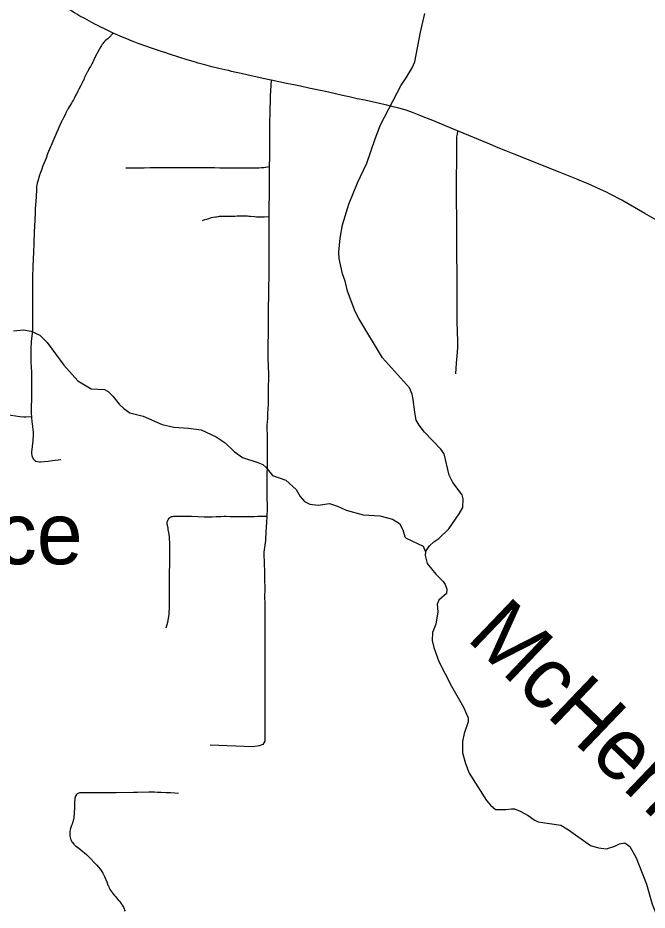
# Model space of a CAD drawing. Extents: x -19 to 366, y -4 to 359.
# Drawn here: x 143.966 to 144.78, y 188.535 to 189.689 of the extents above; entities that cross this region are included whole.
import ezdxf

# ---------------------------------------------------------------- set-up
doc = ezdxf.new("R2010")
doc.units = 0
for name, color, linetype in [('R_ROW', 7, 'Continuous'), ('R_ROW Annot', 7, 'Continuous'), ('R_Temp Easement', 7, 'Continuous'), ('Sheet Fence', 7, 'Continuous')]:
    doc.layers.add(name, color=color, linetype=linetype)

msp = doc.modelspace()

# ---------------------------------------------------------------- linework, layer by layer
at = {"layer": 'R_ROW'}
for points in [[(144.0894, 189.669), (144.0789, 189.674), (144.0724, 189.6772), (144.0695, 189.6786), (144.0673, 189.6797), (144.0616, 189.6827), (144.0524, 189.6876), (144.0463, 189.6909), (144.0424, 189.6932), (144.0391, 189.6952), (144.0312, 189.7001), (144.0265, 189.7032), (144.0193, 189.7083), (144.0142, 189.7118), (144.0095, 189.7152), (144.0064, 189.7175), (144.0011, 189.7214), (143.9869, 189.7317), (143.9768, 189.7391)], [(144.0894, 189.669), (144.0838, 189.6629), (144.0834, 189.6626), (144.0822, 189.6616), (144.0809, 189.6606), (144.079, 189.6589), (144.0781, 189.658), (144.0774, 189.6572), (144.0769, 189.6567), (144.0758, 189.6553), (144.0753, 189.6547), (144.0747, 189.6538), (144.074, 189.6528), (144.0721, 189.6496), (144.0709, 189.6475), (144.0689, 189.6438), (144.0679, 189.6419), (144.0648, 189.6357), (144.0641, 189.6342), (144.0628, 189.6315), (144.0616, 189.6291), (144.0598, 189.6259), (144.0589, 189.6245), (144.0579, 189.6225), (144.0563, 189.6194), (144.0557, 189.6184), (144.0539, 189.6148), (144.0531, 189.6131), (144.0519, 189.6105), (144.0512, 189.6091), (144.0502, 189.6069), (144.0496, 189.606), (144.049, 189.6048), (144.0473, 189.6013), (144.0449, 189.5963), (144.0436, 189.5937), (144.043, 189.5924), (144.0414, 189.5894), (144.0407, 189.5881), (144.0391, 189.5852), (144.0378, 189.5828), (144.0367, 189.5808), (144.0354, 189.5785), (144.0333, 189.5749), (144.0324, 189.5735), (144.031, 189.5713), (144.0304, 189.5703), (144.0298, 189.5693), (144.0286, 189.5666), (144.0281, 189.5656), (144.0274, 189.5641), (144.0256, 189.5602), (144.0237, 189.5569), (144.0231, 189.556), (144.023, 189.5556)], [(144.2933, 189.6081), (144.287, 189.6095), (144.2621, 189.615), (144.2549, 189.6165), (144.2482, 189.618), (144.2423, 189.6194), (144.2381, 189.6204), (144.2335, 189.6215), (144.2259, 189.6232), (144.2169, 189.6254), (144.2079, 189.6277), (144.1992, 189.6302), (144.1957, 189.6312), (144.1911, 189.6326), (144.1834, 189.6349), (144.1756, 189.6375), (144.162, 189.6418), (144.1558, 189.6438), (144.1512, 189.6453), (144.1491, 189.646), (144.1399, 189.6491), (144.1301, 189.6526), (144.1216, 189.6556), (144.1173, 189.6572), (144.1116, 189.6594), (144.1092, 189.6604), (144.1054, 189.662), (144.0983, 189.665), (144.0954, 189.6662), (144.0894, 189.669)], [(144.2933, 189.6081), (144.2923, 189.5876), (144.2917, 189.5649), (144.2915, 189.5545), (144.2915, 189.543), (144.2912, 189.5311), (144.2912, 189.5236), (144.2912, 189.5167), (144.2912, 189.5093), (144.2911, 189.4961)], [(144.5346, 189.5424), (144.5005, 189.5566), (144.4943, 189.5591), (144.4847, 189.5629), (144.4763, 189.5661), (144.468, 189.5691), (144.4585, 189.5719), (144.4496, 189.5742), (144.4432, 189.5757), (144.4147, 189.582), (144.4048, 189.5841), (144.3945, 189.5864), (144.3855, 189.5884), (144.375, 189.5908), (144.3636, 189.5932), (144.342, 189.5977), (144.3314, 189.6001), (144.3227, 189.6018), (144.3135, 189.6038), (144.2933, 189.6081)], [(144.023, 189.5556), (144.019, 189.5467), (144.0181, 189.5448), (144.0163, 189.5406), (144.0097, 189.5256), (144.0089, 189.5237), (144.0081, 189.5217), (144.0045, 189.5128), (144.0024, 189.5074), (143.9998, 189.501), (143.9984, 189.4972), (143.9965, 189.4916), (143.9954, 189.4888), (143.9941, 189.4851), (143.9916, 189.4775), (143.9913, 189.4763), (143.991, 189.4748), (143.9905, 189.4727), (143.9901, 189.4701), (143.9899, 189.4674), (143.9895, 189.4568), (143.9892, 189.452), (143.9885, 189.4414), (143.9883, 189.4371), (143.9877, 189.427), (143.987, 189.4121), (143.9868, 189.3974), (143.9862, 189.3854), (143.9858, 189.3769), (143.9854, 189.3664), (143.9851, 189.3542), (143.985, 189.3447), (143.9849, 189.3373), (143.9849, 189.3272), (143.9848, 189.3108), (143.9849, 189.3049), (143.9849, 189.3012), (143.985, 189.2936), (143.9849, 189.2922), (143.9847, 189.2838), (143.9845, 189.2811), (143.9836, 189.2735), (143.9833, 189.2701), (143.9826, 189.2599), (143.9826, 189.2557), (143.9827, 189.2446), (143.9833, 189.2361), (143.9835, 189.2319), (143.9837, 189.2136), (143.9837, 189.2059), (143.9837, 189.2005), (143.9832, 189.1809), (143.9833, 189.1767), (143.9834, 189.1733)], [(144.7917, 189.4269), (144.7767, 189.4356), (144.747, 189.4527), (144.732, 189.4607), (144.727, 189.4632), (144.7195, 189.4668), (144.7138, 189.4694), (144.7079, 189.472), (144.7013, 189.4748), (144.6949, 189.4774), (144.6885, 189.4799), (144.667, 189.4885), (144.6077, 189.5122), (144.597, 189.5165), (144.5869, 189.5206), (144.5761, 189.5251), (144.5346, 189.5424)], [(144.2911, 189.4961), (144.2839, 189.4949), (144.2809, 189.4946), (144.2776, 189.4944), (144.2739, 189.4943), (144.2702, 189.4942), (144.2628, 189.4942), (144.2557, 189.4942), (144.2483, 189.4943), (144.243, 189.4943), (144.2345, 189.4943), (144.2271, 189.4944), (144.2202, 189.4946), (144.2107, 189.4946), (144.2017, 189.4945), (144.1931, 189.4946), (144.1863, 189.4947), (144.1778, 189.4947), (144.1704, 189.4946), (144.163, 189.4946), (144.1561, 189.4945), (144.1492, 189.4945), (144.1418, 189.4945), (144.137, 189.4945), (144.1291, 189.4944), (144.1222, 189.4944), (144.1158, 189.4944), (144.1089, 189.4943), (144.1055, 189.4941)], [(144.2911, 189.4961), (144.291, 189.4874), (144.291, 189.4809), (144.291, 189.4736), (144.2909, 189.4638), (144.2908, 189.4554), (144.2906, 189.4489), (144.2906, 189.4319)], [(144.2906, 189.4319), (144.2905, 189.4169), (144.2903, 189.4052), (144.2905, 189.3895), (144.2904, 189.3653), (144.2903, 189.357), (144.2903, 189.3505), (144.2902, 189.3444), (144.2901, 189.3379), (144.29, 189.3314), (144.2898, 189.3118), (144.2898, 189.2974), (144.2898, 189.2858), (144.2897, 189.2802), (144.2893, 189.2668), (144.2892, 189.2584), (144.2891, 189.2496), (144.2896, 189.2371), (144.29, 189.2287), (144.29, 189.2222), (144.2898, 189.2121), (144.2895, 189.2023), (144.2894, 189.1971), (144.2894, 189.1892), (144.2889, 189.1771), (144.2886, 189.1706), (144.288, 189.1618), (144.288, 189.159), (144.2882, 189.1479), (144.2882, 189.1391), (144.2881, 189.1312), (144.2881, 189.1112), (144.2878, 189.0954), (144.2878, 189.0885), (144.2878, 189.0817), (144.2878, 189.0738), (144.288, 189.0674), (144.2881, 189.059), (144.2881, 189.0538), (144.2878, 189.0443)], [(144.2878, 189.0443), (144.2875, 189.0359), (144.2872, 189.0309), (144.2863, 189.0149), (144.2861, 189.0128), (144.2839, 188.9979), (144.2839, 188.997), (144.2845, 188.9821), (144.2849, 188.9736), (144.2849, 188.9646), (144.2851, 188.9492), (144.285, 188.9412), (144.2852, 188.9303), (144.2855, 188.9253)]]:
    msp.add_lwpolyline(points, dxfattribs=at)
at = {"layer": 'R_ROW Annot'}
for points in [[(144.5346, 189.5424), (144.534, 189.5384), (144.5333, 189.5347), (144.5331, 189.533), (144.5331, 189.5295), (144.5329, 189.5063), (144.5327, 189.4796), (144.5327, 189.471), (144.5329, 189.411), (144.5329, 189.3918), (144.5329, 189.3865), (144.533, 189.383), (144.5332, 189.3728), (144.5334, 189.3679), (144.5335, 189.3619), (144.5335, 189.3579), (144.5334, 189.3461), (144.5334, 189.3351), (144.5334, 189.3249), (144.5334, 189.3095), (144.5335, 189.3028), (144.5336, 189.2979), (144.5337, 189.294), (144.5338, 189.2843), (144.534, 189.2792), (144.5342, 189.2743), (144.5344, 189.271), (144.5346, 189.2664), (144.5345, 189.263), (144.534, 189.2565), (144.5327, 189.2423), (144.5319, 189.2284)], [(144.2047, 189.4267), (144.2076, 189.4277), (144.2101, 189.4284), (144.2131, 189.4294), (144.2163, 189.4303), (144.2186, 189.4308), (144.2216, 189.4313), (144.2229, 189.4315), (144.2253, 189.4318), (144.2268, 189.432), (144.2287, 189.4321), (144.2315, 189.4322), (144.2336, 189.4322), (144.2362, 189.4322), (144.24, 189.4321), (144.2416, 189.4321), (144.2445, 189.4321), (144.2466, 189.4322), (144.2495, 189.4325), (144.2519, 189.4326), (144.2533, 189.4326), (144.2554, 189.4326), (144.2572, 189.4327), (144.2587, 189.4327), (144.2627, 189.4325), (144.2648, 189.4324), (144.2669, 189.4322), (144.272, 189.4317), (144.2745, 189.4315), (144.2767, 189.4314), (144.2795, 189.4313), (144.2824, 189.4312), (144.2843, 189.4313), (144.2906, 189.4319)], [(143.9037, 189.1612), (143.9061, 189.1626), (143.9089, 189.1642), (143.9109, 189.1655), (143.9119, 189.1664), (143.914, 189.1679), (143.9166, 189.1698), (143.9176, 189.1705), (143.9188, 189.1717), (143.9201, 189.1729), (143.9236, 189.1755), (143.9241, 189.1757), (143.9254, 189.1764), (143.9258, 189.1766), (143.9266, 189.1768), (143.9281, 189.1768), (143.9319, 189.1765), (143.9403, 189.1759), (143.9538, 189.1755), (143.9573, 189.1751), (143.9683, 189.1734), (143.9735, 189.1726), (143.9761, 189.1726), (143.9834, 189.1733)], [(143.9834, 189.1733), (143.9834, 189.173), (143.9841, 189.1661), (143.9844, 189.164), (143.9849, 189.1598), (143.9856, 189.1528), (143.9857, 189.1498), (143.9852, 189.1419), (143.9838, 189.1269), (143.9838, 189.1253), (143.984, 189.1227), (143.9843, 189.1216), (143.9858, 189.1187), (143.9861, 189.1182), (143.9866, 189.1177), (143.988, 189.1164), (143.9894, 189.1155), (143.9898, 189.1153), (143.9918, 189.115), (143.9939, 189.1148), (143.9954, 189.1148), (144.005, 189.1156), (144.0107, 189.1163), (144.0214, 189.1177)], [(144.1576, 188.9002), (144.1598, 188.9075), (144.1603, 188.9095), (144.1612, 188.9152), (144.1615, 188.9172), (144.1621, 188.928), (144.1619, 188.9379), (144.1619, 188.9461), (144.162, 188.9706), (144.1621, 188.9742), (144.1624, 188.9798), (144.1624, 188.9821), (144.1625, 188.988), (144.1626, 188.9967), (144.1626, 188.9985), (144.1625, 189.0074), (144.1624, 189.0102), (144.1621, 189.015), (144.1619, 189.0173), (144.1614, 189.0211), (144.1605, 189.0272), (144.1601, 189.0295), (144.159, 189.034), (144.1591, 189.0354), (144.1592, 189.0369), (144.1597, 189.0389), (144.1602, 189.0401), (144.1606, 189.0407), (144.1614, 189.0416), (144.1625, 189.0426), (144.1642, 189.0437), (144.1646, 189.0438), (144.1655, 189.044), (144.1672, 189.0442), (144.1718, 189.0443), (144.1779, 189.0443), (144.1818, 189.0443), (144.1854, 189.0444), (144.1884, 189.0443), (144.1904, 189.0442), (144.207, 189.0433), (144.2106, 189.0433), (144.2172, 189.0436), (144.2223, 189.0439), (144.2282, 189.0441), (144.2323, 189.0442), (144.2352, 189.0443), (144.2404, 189.0441), (144.249, 189.0438), (144.2526, 189.0438), (144.2677, 189.0441), (144.2719, 189.0441), (144.2758, 189.0442), (144.2878, 189.0443)], [(144.2855, 188.9253), (144.2851, 188.7534), (144.2827, 188.7493), (144.278, 188.7475), (144.2698, 188.7463), (144.2144, 188.7481)], [(144.1737, 188.686), (144.1689, 188.6862), (144.1635, 188.6865), (144.1579, 188.6868), (144.1514, 188.687), (144.1466, 188.6873), (144.1427, 188.6874), (144.1376, 188.6876), (144.1351, 188.6876), (144.1207, 188.6872), (144.1154, 188.6871), (144.0931, 188.6867), (144.0883, 188.6867), (144.0847, 188.6867), (144.0802, 188.6867), (144.072, 188.6865), (144.0658, 188.6865), (144.0537, 188.6866), (144.0517, 188.6867), (144.0478, 188.6868), (144.0458, 188.6865), (144.0447, 188.6863), (144.0436, 188.6858), (144.0427, 188.6852), (144.0418, 188.6845), (144.0405, 188.6822), (144.04, 188.6811), (144.0397, 188.68), (144.0396, 188.6787), (144.0394, 188.6748), (144.0393, 188.6734), (144.0391, 188.6703), (144.039, 188.6663), (144.0389, 188.6617), (144.0388, 188.6591), (144.0385, 188.6563), (144.0383, 188.6545), (144.0378, 188.652), (144.0376, 188.6512), (144.0373, 188.6502), (144.0368, 188.6482), (144.0361, 188.6461), (144.0355, 188.6443), (144.0345, 188.6418), (144.034, 188.6404), (144.0336, 188.639), (144.0333, 188.637), (144.0331, 188.6351), (144.033, 188.6328), (144.033, 188.6314), (144.0337, 188.6288), (144.0342, 188.6272), (144.0348, 188.6256), (144.0358, 188.6235), (144.0365, 188.6224), (144.0384, 188.6202), (144.0396, 188.6191), (144.041, 188.6179), (144.0431, 188.6163), (144.0447, 188.6151), (144.0473, 188.6132), (144.0549, 188.6069), (144.0577, 188.6041), (144.0674, 188.5942), (144.0682, 188.5932), (144.07, 188.591), (144.0726, 188.5876), (144.0737, 188.5861), (144.0757, 188.583), (144.0768, 188.581), (144.0781, 188.5785), (144.0794, 188.5754), (144.0798, 188.5745), (144.0808, 188.5717), (144.0813, 188.5705), (144.0825, 188.5674), (144.083, 188.5664), (144.0836, 188.5649), (144.0841, 188.5638), (144.0854, 188.5613), (144.0864, 188.5596), (144.0877, 188.5579), (144.0885, 188.5568), (144.091, 188.5538), (144.0921, 188.5525), (144.0963, 188.5477), (144.097, 188.547), (144.0977, 188.5461), (144.0993, 188.5441), (144.1005, 188.5423), (144.101, 188.5416), (144.1017, 188.5403), (144.1024, 188.539), (144.1034, 188.5368), (144.104, 188.5351), (144.1045, 188.5335)]]:
    msp.add_lwpolyline(points, dxfattribs=at)
at = {"layer": 'R_Temp Easement'}
for points in [[(144.4932, 188.9982), (144.4983, 189.006), (144.5037, 189.0112), (144.5104, 189.0157), (144.5232, 189.0279), (144.5364, 189.0472), (144.5411, 189.0557), (144.5418, 189.0666), (144.5405, 189.0721), (144.5285, 189.0878), (144.5235, 189.0974), (144.5171, 189.1249), (144.5127, 189.131), (144.4919, 189.1531), (144.4849, 189.1618), (144.4811, 189.1683), (144.4791, 189.1787), (144.4771, 189.195), (144.476, 189.2022), (144.4723, 189.2102), (144.4376, 189.2491), (144.4069, 189.2997), (144.4019, 189.309), (144.3923, 189.3351), (144.3892, 189.3482), (144.3856, 189.3575), (144.3813, 189.3774), (144.3809, 189.3856), (144.3825, 189.4036), (144.3857, 189.4211), (144.3941, 189.4479), (144.4052, 189.4751), (144.4172, 189.5008), (144.4279, 189.5324), (144.435, 189.5504), (144.4614, 189.6016), (144.4682, 189.6109), (144.4757, 189.6241), (144.4791, 189.6319), (144.4867, 189.6703), (144.4923, 189.6944)], [(143.9603, 189.2838), (143.9732, 189.2853), (143.9833, 189.2837), (143.9945, 189.2782), (144.0038, 189.2688), (144.0256, 189.2396), (144.0433, 189.2194), (144.0606, 189.2092), (144.0779, 189.2083), (144.0827, 189.2057), (144.0888, 189.1996), (144.097, 189.1892), (144.1029, 189.1836), (144.1109, 189.1779), (144.1278, 189.1738), (144.1527, 189.1627), (144.1675, 189.1593), (144.1868, 189.1581), (144.203, 189.1559), (144.2224, 189.147), (144.2342, 189.1393), (144.2458, 189.1278), (144.2566, 189.12), (144.2764, 189.1137)], [(144.2764, 189.1137), (144.2825, 189.111), (144.2867, 189.1076), (144.2952, 189.097), (144.3125, 189.0908), (144.3259, 189.0788), (144.3308, 189.0697), (144.3367, 189.0632), (144.3434, 189.0597), (144.3544, 189.0586), (144.3688, 189.0609), (144.3793, 189.0575), (144.3905, 189.0523), (144.4125, 189.0463), (144.4342, 189.0447), (144.4503, 189.0407), (144.4594, 189.0347), (144.4638, 189.0267), (144.4665, 189.0178), (144.468, 189.0161), (144.4899, 189.0056), (144.4932, 188.9982), (144.4924, 188.9936), (144.4953, 188.9832), (144.5062, 188.9694), (144.5159, 188.9601), (144.5186, 188.9562), (144.5205, 188.9501), (144.52, 188.9446), (144.5101, 188.9356), (144.5083, 188.9305), (144.5089, 188.9208), (144.5063, 188.9047), (144.5022, 188.8938), (144.5016, 188.8838), (144.5036, 188.8745), (144.5101, 188.8563), (144.5265, 188.8246), (144.542, 188.7975), (144.5482, 188.7835), (144.548, 188.7786), (144.5431, 188.7636), (144.5409, 188.7529), (144.541, 188.7383), (144.5446, 188.7246), (144.5496, 188.7123), (144.572, 188.6767), (144.5769, 188.6709), (144.5834, 188.6652), (144.5969, 188.6651), (144.6041, 188.6662), (144.6081, 188.6659), (144.6153, 188.6632), (144.6259, 188.6572), (144.6335, 188.6517), (144.6387, 188.6493), (144.6679, 188.6447), (144.6778, 188.639), (144.7063, 188.6186), (144.7168, 188.6155), (144.7269, 188.6145), (144.738, 188.6178), (144.7439, 188.6209), (144.7507, 188.622), (144.7572, 188.6175), (144.7654, 188.6026), (144.7787, 188.5684)], [(144.7787, 188.5684), (144.786, 188.5426), (144.7958, 188.5196), (144.8023, 188.4959), (144.8057, 188.4886), (144.813, 188.4818)]]:
    msp.add_lwpolyline(points, dxfattribs=at)
at = {"layer": 'Sheet Fence'}
for points in [[(146.7783, 1.697), (146.5788, 10.3131), (146.3785, 18.9294), (146.1776, 27.5458), (145.9759, 36.1624), (145.7736, 44.7791), (145.5705, 53.396), (145.3668, 62.013), (145.1624, 70.6301), (144.9572, 79.2474), (144.7514, 87.8648), (144.5449, 96.4823), (144.3377, 105.1), (144.1299, 113.7179), (143.9213, 122.3359), (143.712, 130.954), (143.5021, 139.5723), (143.2915, 148.1907), (143.0802, 156.8092), (142.8682, 165.4279), (142.6555, 174.0468), (142.4422, 182.6658), (142.2282, 191.2849), (142.0135, 199.9042), (141.7981, 208.5236), (141.582, 217.1432), (141.3653, 225.7629), (141.1479, 234.3828), (140.9298, 243.0028), (140.711, 251.623), (140.4916, 260.2433), (140.2715, 268.8638), (140.0508, 277.4844), (139.8293, 286.1051), (139.6072, 294.726), (139.3845, 303.3471), (139.161, 311.9683), (138.937, 320.5896), (138.7122, 329.2111), (138.4868, 337.8328), (138.2607, 346.4546)], [(0, 189.5162), (7.1121, 189.5206), (14.2243, 189.5339), (21.3364, 189.556), (28.4484, 189.5869), (35.5605, 189.6267), (42.6725, 189.6754), (49.7844, 189.7329), (56.8962, 189.7992), (64.0079, 189.8744), (71.1196, 189.9584), (78.2311, 190.0512), (85.3425, 190.1529), (92.4538, 190.2635), (99.5649, 190.3829), (106.6759, 190.5111), (113.7867, 190.6482), (120.8974, 190.7941), (128.0078, 190.9489), (135.1181, 191.1125), (142.2282, 191.2849), (149.338, 191.4662), (156.4476, 191.6563), (163.5569, 191.8553), (170.666, 192.0631), (177.7749, 192.2798), (184.8835, 192.5053), (191.9917, 192.7396), (199.0997, 192.9828), (206.2074, 193.2348), (213.3147, 193.4956), (220.4218, 193.7653), (227.5285, 194.0438), (234.6348, 194.3312), (241.7408, 194.6274), (248.8464, 194.9324), (255.9516, 195.2463), (263.0564, 195.569), (270.1608, 195.9005), (277.2648, 196.2409), (284.3683, 196.5901), (291.4715, 196.9481), (298.5741, 197.315), (305.6763, 197.6907), (312.7781, 198.0753), (319.8793, 198.4686), (326.9801, 198.8708), (334.0804, 199.2818), (341.1801, 199.7017)], [(0, 180.8999), (7.1228, 180.9044), (14.2457, 180.9176), (21.3685, 180.9397), (28.4912, 180.9706), (35.614, 181.0103), (42.7366, 181.0589), (49.8592, 181.1163), (56.9818, 181.1825), (64.1042, 181.2575), (71.2266, 181.3414), (78.3488, 181.4341), (85.4709, 181.5357), (92.5929, 181.646), (99.7147, 181.7652), (106.8364, 181.8933), (113.9579, 182.0301), (121.0793, 182.1758), (128.2005, 182.3303), (135.3214, 182.4936), (142.4422, 182.6658), (149.5627, 182.8468), (156.683, 183.0366), (163.8031, 183.2352), (170.9229, 183.4427), (178.0425, 183.659), (185.1617, 183.8841), (192.2807, 184.1181), (199.3994, 184.3608), (206.5178, 184.6124), (213.6359, 184.8728), (220.7537, 185.1421), (227.8711, 185.4201), (234.9881, 185.707), (242.1048, 186.0027), (249.2212, 186.3073), (256.3371, 186.6206), (263.4526, 186.9428), (270.5678, 187.2738), (277.6825, 187.6136), (284.7968, 187.9622), (291.9107, 188.3197), (299.0241, 188.6859), (306.1371, 189.061), (313.2495, 189.4449), (320.3615, 189.8377), (327.4731, 190.2392), (334.5841, 190.6495), (341.6946, 191.0687)]]:
    msp.add_spline(points, degree=3, dxfattribs=at)

# ---------------------------------------------------------------- texts
at = {"layer": 'R_Temp Easement'}
msp.add_text('Florance', height=0.08, dxfattribs=at).set_placement((143.6337, 188.9822))
msp.add_text('McHenry', height=0.08, rotation=316.2532, dxfattribs=at).set_placement((144.5445, 188.8857))

doc.saveas('drawing.dxf')
